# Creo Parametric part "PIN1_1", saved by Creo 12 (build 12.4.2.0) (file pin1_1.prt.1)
Units: Custom; MM, KILOGRAM, SECS

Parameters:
  PTC_WM_ITERATION = "0"
  PTC_WM_VERSION = "-.0"
  PTC_WM_LIFECYCLE_STATE = "In Work"
  PTC_WM_LIFECYCLE = "MO_CADDocument"
  PTC_WM_CREATED_BY = "Maximilian Roepper (Z0017RMS: MO)"
  PTC_WM_CREATED_ON = "18-Sep-26 11:36:42 AM"
  PTC_WM_MODIFIED_BY = "Maximilian Roepper (Z0017RMS: MO)"
  PTC_WM_MODIFIED_ON = "18-Sep-26 11:36:46 AM"
  PDMLINKNUMBER = "PDM000071454978"
  PTC_WM_NAME = "pin1_1.prt"
  PTC_WM_NUMBER = "PDM000071454978"

Other parameters: WEIGHT, WEIGHT_FACTOR, WEIGHT_ADD, _MASS_TEMP, _DIFF_TEMP, MC_ERRORS, SUPPLIER

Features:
  1. coordinate system
  2. datum plane "PRT_YZ"
  3. datum plane "PRT_XY"
  4. datum plane "PRT_XZ"
  5. coordinate system
  6. datum axis
  7. datum axis
  8. datum axis
  9. coordinate system
  10. imported feature

Other named items: PRT, SIEMENS_MO, DRW_VIEW_ORG, PRT_X, PRT_Y, PRT_Z, CS0, ROUGH_GROB

Layers: 00_STD_CSYS-KSYS, 01_STD_PLANES-EBENEN, 02_STD_AXES-ACHSEN, 03_STD_CSYS-KSYS, 24_IMPORT_FEAT-IMPORT_KE

Surfaces: 10 plane, 4 cylinder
